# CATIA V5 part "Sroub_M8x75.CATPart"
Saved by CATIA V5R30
Part number: Sroub_M8x75
Definition: E 1200_8x75_3
Nomenclature: E 1200_8x75_3
Source: Unknown
Description: PART--DESC
Bounding box of the stored display mesh (mm): x -136 to -123, y -24.99 to -12.01, z 11.2 to 94.2
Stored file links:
  E:\Bakalarka\Model\Forma_v7\Sroub_M8x75.CATPart
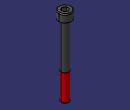
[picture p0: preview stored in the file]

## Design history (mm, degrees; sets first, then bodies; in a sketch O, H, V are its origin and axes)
Body1 "MANIFOLD_SOLID_BREP #3610" (main body)
  Solid1: solid without history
